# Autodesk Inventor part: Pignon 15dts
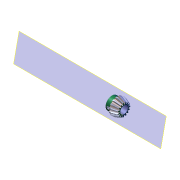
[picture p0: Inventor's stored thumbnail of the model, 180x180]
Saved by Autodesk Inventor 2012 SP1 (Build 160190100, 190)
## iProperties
Created: 2014-12
Part Number: Pignon 15dts
Material: Default
Document SubType Name: Modeling
Designer: Bruno
Density: 1 g/cm^3
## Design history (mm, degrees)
node "Pignon 15dts1"
node "Plan de construction1"
sketch "Esquisse3"
  geometry: L1 (16.279, -6.41)-(16.279, -4.886) reference; L2 (21.189, -8.381)-(16.279, -6.41) reference; L3 (23.689, -8.4)-(16.279, -5.424); L4 (24.399, -6.65)-(24.399, 6.65) reference; L5 (24.399, 0)-(15.145, 0); 2 further points
  constraints: 4 end point, 1 midpoint, 1 parallel, 1 perpendicular, 1 point on line, 3 other
feature "SrfRévolution1" sketch "Esquisse3" dims angle "d4" = 90 deg
node "Pignon 15dts"
node "Base1"
node "Boucle projetée1"
body "Srf2"
